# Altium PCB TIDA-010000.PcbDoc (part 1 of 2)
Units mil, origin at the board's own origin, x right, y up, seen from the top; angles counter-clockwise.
Board outline 6158.37 x 2561.06 mil, 2 copper layers (Top Layer, Bottom Layer), stack 62 mil thick; 145 components, 51 nets, 285 pads, 57 vias.
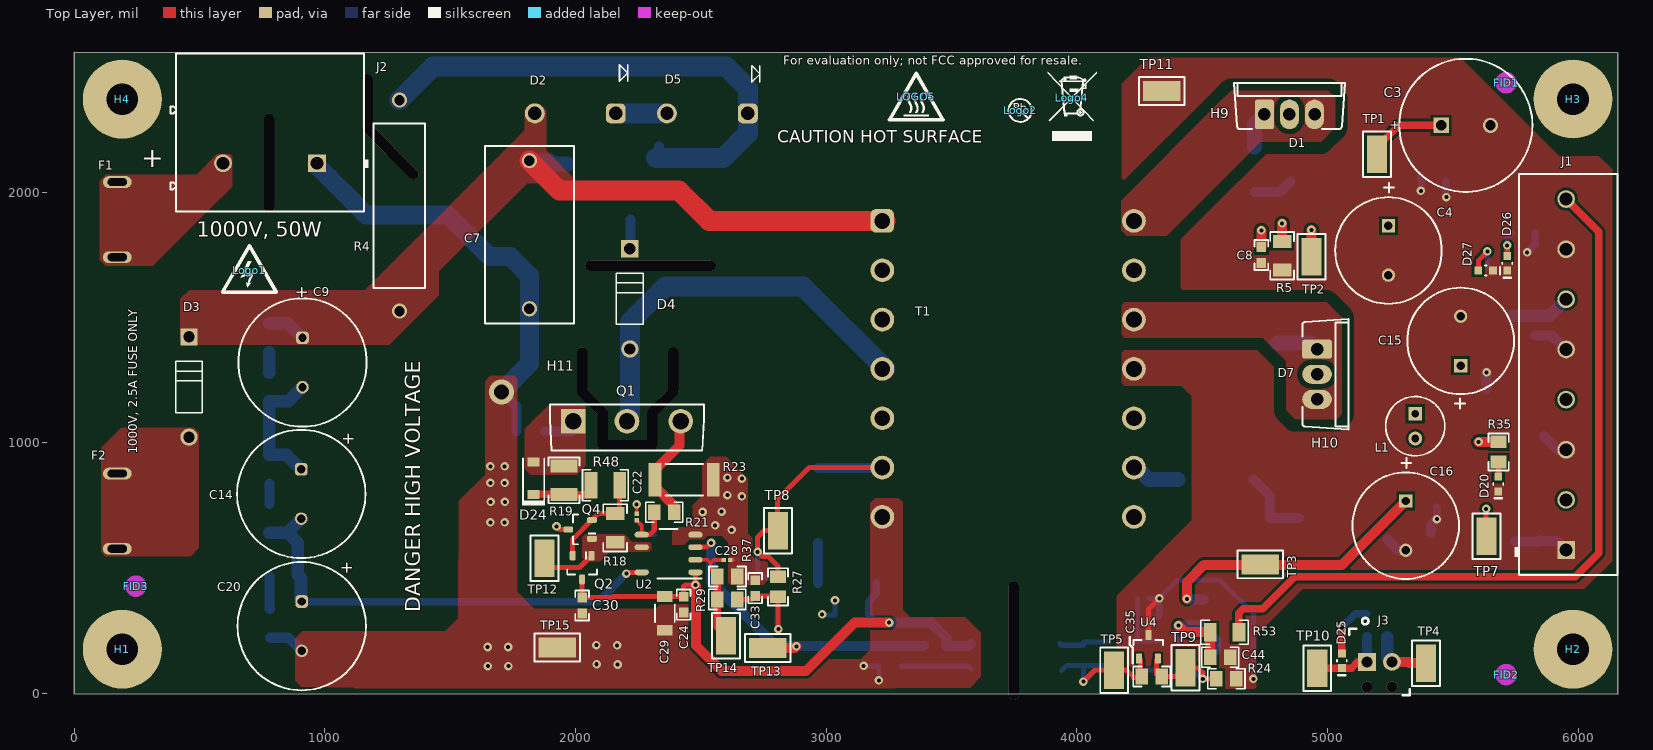
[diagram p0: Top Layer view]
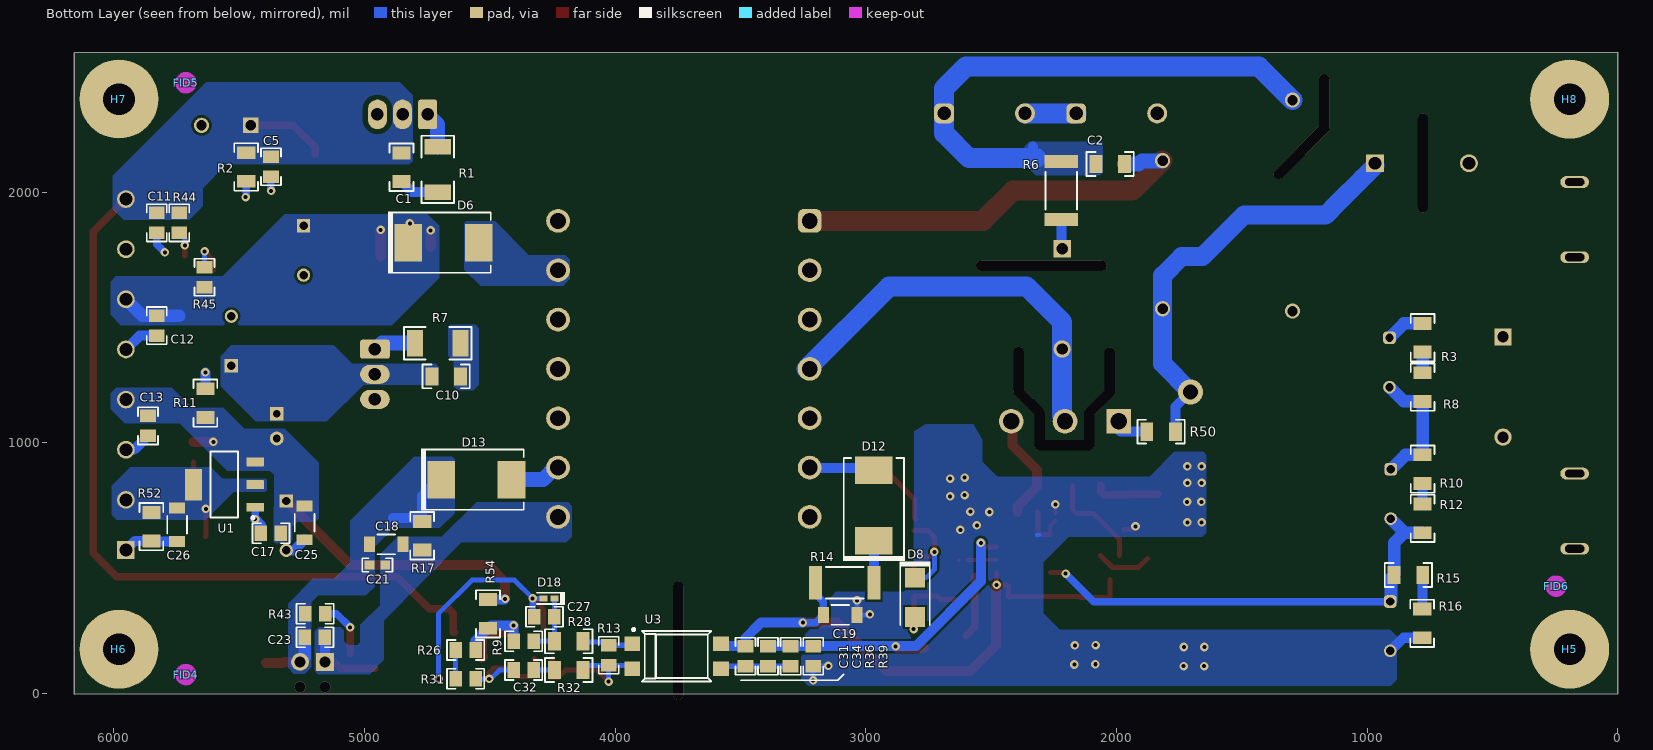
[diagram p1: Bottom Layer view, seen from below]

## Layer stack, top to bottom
Top Solder: solder mask 0.4, Solder Resist, Dk 3.5
Top Layer: signal copper 1.4
Dielectric1: core 59.2, FR-4 Hign Tg, Dk 4.8
Bottom Layer: signal copper 1.4
Bottom Solder: solder mask 0.4, Solder Resist, Dk 3.5

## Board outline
0,0 6158.37,-2 6157.71,2557.06 0,2559.06

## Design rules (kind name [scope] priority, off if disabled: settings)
AcuteAngle [All] p1: minimum=4.50000000000000E+0001 checktracksonly=FALSE
AssemblyTestPointUsage [All] p1: valid=2
BoardOutlineClearance [All] p1: gap=15 ignorepadtopadclearanceinfootprint=FALSE
Clearance "24V Diode" [InNet('24VDC') vs InNet('NetD1_1')] p1: gap=19.68 ignorepadtopadclearanceinfootprint=FALSE
Clearance 5V_Diode [InNet('NetD7_1') vs InNet('NetC10_1')] p2: gap=19.68 ignorepadtopadclearanceinfootprint=FALSE
Clearance Sec_Diode [(InNet('NetD1_1') OR InNet('NetD6_2') OR InNet('NetD7_1')) vs InNet('GND')] p3: gap=49.21 ignorepadtopadclearanceinfootprint=FALSE
Clearance HV_PGND_CLEARANCE [(InNet('VDC') OR InNet('NetC2_2')) vs InNet('PGND')] p4: gap=314.96 ignorepadtopadclearanceinfootprint=FALSE except(0: Text-Hole; 10: Text-Text)
Clearance Clearance_Poly [InPolygon] p5: gap=10 ignorepadtopadclearanceinfootprint=FALSE except(0: Arc-Hole Track-Hole SMDPad-Hole THPad-Hole Via-Hole Fill-Hole Poly-Hole Region-Hole Text-Hole; 15: SMDPad-SMDPad; 25: Arc-Arc Arc-Track Arc-SMDPad Arc-THPad Arc-Via Arc-Text Track-Track Track-SMDPad Track-THPad Track-Via Track-Text SMDPad-THPad SMDPad-Via SMDPad-Text THPad-THPad THPad-Via Via-Via Via-Text Fill-Text Poly-Text Region-Text Text-Text)
Clearance HV_NET [InNet('HV_START')] p6: gap=62.99 ignorepadtopadclearanceinfootprint=FALSE
Clearance Clearance_Keepouts [((IsTrack Or IsArc) And Not InPoly) And IsFree and IsKeepOut vs ((IsTrack Or IsArc) And Not InPoly) And IsFree and IsKeepOut] p7: gap=0 ignorepadtopadclearanceinfootprint=FALSE
Clearance Clearance_FiducialMark [IsKeepOut and InComponentClass('FiducialMark') vs IsPad and InComponentClass('FiducialMark')] p8: gap=0 ignorepadtopadclearanceinfootprint=FALSE
Clearance samenet [All] p9: gap=7.87 ignorepadtopadclearanceinfootprint=FALSE except(0: Arc-Hole Track-Hole SMDPad-Hole THPad-Hole Via-Hole Fill-Hole Poly-Hole Region-Hole Text-Hole; 20: THPad-Fill THPad-Poly THPad-Region)
Clearance [All] p10: gap=7.87 ignorepadtopadclearanceinfootprint=FALSE except(0: Arc-Hole Track-Hole SMDPad-Hole THPad-Hole Via-Hole Fill-Hole Poly-Hole Region-Hole Text-Hole; 10: Fill-Fill Fill-Poly Fill-Region Poly-Poly Poly-Region Region-Region; 20: THPad-Fill THPad-Poly THPad-Region)
ComponentClearance ComponentClearance_MountingHoles_FiducialMarks [InComponentClass('Mounting Holes') vs InComponentClass('FiducialMark')] p1: gap=10 collisioncheckmode=3 verticalgap=10 showdistances=FALSE
ComponentClearance ComponentClearance_Shunt [InComponentClass('Header') vs InComponentClass('Shunt')] p2: gap=0 collisioncheckmode=3 verticalgap=0 showdistances=FALSE
ComponentClearance ComponentClearance_Logo [InComponentClass('Logo')] p3: gap=10 collisioncheckmode=3 verticalgap=10 showdistances=FALSE
ComponentClearance ComponentClearance_ScrewToNut [(HasFootprint('NY PMS 440 0025 PH')) vs (HasFootprint('Keystone_1902C'))] p4: gap=5 collisioncheckmode=3 verticalgap=10 showdistances=FALSE
ComponentClearance ComponentClearance_MountingHoles [InComponentClass('Mounting Holes')] p5: gap=250 collisioncheckmode=3 verticalgap=100000 showdistances=FALSE
ComponentClearance ComponentClearance_SmallPassives [HasFootprint('0201*') or HasFootprint('0402*') or HasFootprint('0508') or HasFootprint('0603*') or HasFootprint('0612') or HasFootprint('0805*') or HasFootprint('0815*') or HasFootprint('0830*') or HasFootprint('1206*') or HasFootprint('1210*') or HasFootprint('1808*') or HasFootprint('1812*') or HasFootprint('1825*') or HasFootprint('2010*') or HasFootprint('2220*') or HasFootprint('2225*') or HasFootprint('2512*') or HasFootprint('2728*') or HasFootprint('3518*') vs HasFootprint('0201*') or HasFootprint('0402*') or HasFootprint('0508') or HasFootprint('0603*') or HasFootprint('0612') or HasFootprint('0805*') or HasFootprint('0815*') or HasFootprint('0830*') or HasFootprint('1206*') or HasFootprint('1210*') or HasFootprint('1808*') or HasFootprint('1812*') or HasFootprint('1825*') or HasFootprint('2010*') or HasFootprint('2220*') or HasFootprint('2225*') or HasFootprint('2512*') or HasFootprint('2728*') or HasFootprint('3518*')] p6: gap=12 collisioncheckmode=3 verticalgap=10 showdistances=FALSE
ComponentClearance ComponentClearance_THtoSMT [IsThruComponent vs IsSMTComponent] p7: gap=20 collisioncheckmode=3 verticalgap=30 showdistances=FALSE
ComponentClearance ComponentClearance_THtoTH [IsThruComponent vs IsThruComponent] p8: gap=20 collisioncheckmode=3 verticalgap=30 showdistances=FALSE
ComponentClearance [All] p9: gap=20 collisioncheckmode=3 verticalgap=10 showdistances=FALSE
DiffPairsRouting [All] p1: maxlimit=100 minlimit=10 mostfreqgap=10 toplayer_minwidth=15 toplayer_maxwidth=15 toplayer_prefwidth=15 bottomlayer_minwidth=15 bottomlayer_maxwidth=15 bottomlayer_prefwidth=15 maxuncoupledlength=1000
FabricationTestPointUsage TestPointUsage [All] p1: valid=2 allowmultiple=FALSE
FabricationTestpoint Testpoint [All] p1: side=3 testpointundercomponent=TRUE minsize=40 maxsize=100 preferedsize=60 minholesize=0 maxholesize=40 preferedholesize=32 testpointgrid=1 allowsidetop=TRUE allowsidebottom=TRUE usegrid=TRUE gridtolerance=0.01
FanoutControl Fanout_LCC [IsLCC] p1: bgadir=Out bgaviamode=Centered fanoutstyle=Auto fanoutdirection=Alternating viagrid=1 // Fanout_LCC (Default Rule)
FanoutControl Fanout_BGA [IsBGA] p2: bgadir=Out bgaviamode=Centered fanoutstyle=Auto fanoutdirection=Alternating viagrid=1 // Fanout_BGA (Default Rule)
FanoutControl Fanout_Default [All] p4: bgadir=Out bgaviamode=Centered fanoutstyle=Auto fanoutdirection=Alternating viagrid=1 // Fanout_Default (Default Rule)
FanoutControl Fanout_Small [(CompPinCount < 5)] p5: bgadir=Out bgaviamode=Centered fanoutstyle=Auto fanoutdirection=OutThenIn viagrid=1 // Fanout_Small (Default Rule)
HoleSize [All] p1: absolutevalues=TRUE maxlimit=251 minlimit=7.87 maxpercent=80.000 minpercent=20.000
MinimumAnnularRing MinimumAnnularRing_ThermalPadVias [IsVia and InAnyComponent] p1: minimumring=5.91
MinimumAnnularRing [All] p2: minimumring=8
MinimumSolderMaskSliver MinimumSolderMaskSliver_Logo [InComponentClass('Logo') vs InComponentClass('Logo')] p1: minsoldermaskwidth=0.7
MinimumSolderMaskSliver [All] p2: minsoldermaskwidth=3.94
PlaneConnect [All] p1: planeconnectstyle=Relief reliefexpansion=10 reliefentries=4 reliefconductorwidth=10 reliefairgap=10
PolygonConnect [All] p1: connectstyle=Direct reliefconductorwidth=10 reliefentries=4 polygonreliefangle="90 Angle" airgapwidth=10
RoutingVias ThermalPadVias [IsVia and InAnyComponent] p1: holewidth=7.87 width=19.68 viastyle="Through Hole" minholewidth=7.87 minwidth=19.68 maxholewidth=12.99 maxwidth=23.62
RoutingVias [All] p2: holewidth=16 width=34 viastyle="Through Hole" minholewidth=7.87 minwidth=26 maxholewidth=40 maxwidth=65
SilkToBoardRegionClearance [Not ((IsComment or IsDesignator) And (Hide <> 'False')) and not InRegion(1000,500,4000,800)] p1:
SilkToSilkClearance SilkToSilkClearance_Pb-FreeLogo [(HasFootprint('Pb-Free_Overlay_Medium') OR HasFootprint('Pb-Free_Overlay_Small')) vs (HasFootprint('Pb-Free_Overlay_Medium') OR HasFootprint('Pb-Free_Overlay_Small'))] p1: silktosilkclearance=0
SilkToSilkClearance [All] p2: silktosilkclearance=4
SilkToSolderMaskClearance SilkToComponentPadClearance [(IsPad or IsFill or IsRegion) and InAnycomponent] p1: minsilkscreentomaskgap=5 clearancetoexposedcopper=TRUE
SilkToSolderMaskClearance "Silk to Solder Mask Opening" [All] p2: minsilkscreentomaskgap=4 clearancetoexposedcopper=FALSE
SolderMaskExpansion [All] p1: expansion=1.97
Width [All] p1: maxlimit=100 minlimit=6 preferedwidth=10 checkconnectedcopper=TRUE
15 further rules are at their usual default settings.

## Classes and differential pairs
component class AssemblyNote: ZZ1 ZZ2 ZZ3 ZZ4
component class FiducialMark: FID1 FID2 FID3 FID4 FID5 FID6
component class EVM_Hardware: FID1 FID2 FID3 FID4 FID5 FID6 H1 H2 H3 H4 H5 H6 H7 H8 Logo1 Logo2 Logo3 Logo4 LOGO5 ZZ1 ZZ2 ZZ3 ZZ4
component class "Mounting Holes": H1 H2 H3 H4
component class "Pg1 Flyback Converter": C1 C2 C3 C4 C5 C7 C8 C9 C10 C11 C12 C13 C14 C15 C16 C17 C18 C19 C20 C21 C22 C23 C24 C25 C26 C27 C28 C29 C30 C31 C32 C33 C34 C35 C44 D1 D2 D3 D4 D5 D6 D7 D8 D12 D13 D18 D20 D24 D25 D26 D27 F1 F2 H9 H10 H11 J1 J2 J3 L1 Q1 Q2 Q4 R1 R2 R3 R4 R5 R6 R7 R8 R9 R10 R11 R12 R13 R14 R15 R16 R17 R18 R19 R21 R23 R24 R26 R27 R28 R29 R31 R32 R35 R36 R37 R39 R43 R44 R45 R48 R50 R52 R53 R54 T1 TP1 TP2 TP3 TP4 TP5 TP7 TP8 TP9 TP10 TP11 TP12 TP13 TP14 TP15 U1 U2 U3 U4

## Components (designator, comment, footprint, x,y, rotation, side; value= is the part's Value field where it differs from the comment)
C1 "GRM31A5C2J331JW01D" 1206 4852.44,2100 r270 bottom value=330pF
C2 "GRM31BR73A472KW01L" 1206 2025.22,2113 r0 bottom value=4700pF
C3 "UBT1H471MHD1TO" BT_1250x2500 5551.83,2267 r0 top value=470uF
C4 "UBT1V331MPD1TD" BT_1000x2000 5243.22,1768 r270 top value=330uF
C5 "C0805C104K5RACTU" 0805_HV 5373.31,2102 r270 bottom value=0.1uF
C7 "B32672L1333J000" B32672_1800x900x1750 1816.22,1831 r270 top value=0.033uF
C8 "GMK107AB7105KAHT" 0603 4736.22,1750 r270 top value=1uF
C9 "450BXW47MEFC12.5X35" BXW_1250x3500 910.91,1321 r270 top locked value=47uF
C10 "GRM31A5C2J331JW01D" 1206 4674.22,1265.52 r180 bottom value=330pF
C11 "C0805C104K5RACTU" 0805_HV 5829.16,1878 r270 bottom value=0.1uF
C12 "C0805C104K5RACTU" 0805_HV 5829.16,1468 r270 bottom value=0.1uF
C13 "C0805C104K5RACTU" 0805_HV 5863.88,1068 r270 bottom value=0.1uF
C14 "450BXW47MEFC12.5X35" BXW_1250x3500 905.91,796.53 r270 top locked value=47uF
C15 "UBT1E471MPD1TD" BT_1000x2000 5531.22,1407 r90 top value=470uF
C16 "UBT1E471MPD1TD" BT_1000x2000 5312.22,670 r270 top value=470uF
C17 "GRM219R71E105KA88D" 0805_HV 5373.31,640 r0 bottom value=1uF
C18 "C3216X7R1E106M160AE" 1206_190 4913.22,595.76 r180 bottom value=10uF
C19 "C3216X7R1V106K160AC" 1206_180 3102.22,314 r180 bottom value=10uF
C20 "450BXW47MEFC12.5X35" BXW_1250x3500 907.91,269 r270 top value=47uF
C21 "C1608X7R1E104K080AA" 0603 4948.83,513 r180 bottom value=0.1uF
C22 "GRM033R71E151KA01D" 0201 2244.22,704.9 r90 top value=150pF
C23 "C0805C104K5RACTU" 0805_HV 5197.88,225 r180 bottom value=0.1uF
C24 "GMK107AB7105KAHT" 0603 2431.22,355 r270 top value=1uF
C25 "C3216X7R1E106M160AE" 1206_190 5239.22,681 r270 bottom value=10uF
C26 "C3216X7R1E106M160AE" 1206_190 5747.88,674 r270 bottom value=10uF
C27 "C0805C104K5RACTU" 0805_HV 4282.28,307 r180 bottom value=0.1uF
C28 "GCM0335C1E220JD03D" 0201_033 2605.22,532.81 r0 top value=22pF
C29 "C3216X7R1V106K160AC" 1206_180 2356.22,320 r270 top value=10uF
C30 "GMK107AB7105KAHT" 0603 2026.65,351.4 r270 top value=1uF
C31 "C2012X7R1H474K125AB" 0805_HV 3480.09,149.18 r270 bottom value=0.47uF
C32 "C2012X7R1H474K125AB" 0805_HV 4365.09,94.18 r180 bottom value=0.47uF
C33 "C1608X7R2A102K080AA" 0603 2716.91,421 r90 top value=1000pF
C34 "08055C473JAT2A" 0805_HV 3390.09,149.18 r90 bottom value=0.047uF
C35 "08055C473JAT2A" 0805_HV 4298.69,68 r0 top value=0.047uF
C44 "C0805C104K5RACTU" 0805_HV 4572.37,145 r0 top value=0.1uF
D1 "MBR20200CTTU" TO-220AB 4848.37,2310.88 r0 top value=200V
D2 "1.5KE200A-E3/54" DO-201AA_Vertical 1837.8,2314.78 r180 top value=200V
D3 "BYX10GP-E3/54" DO-41 458.37,1223.12 r270 top value=1600V
D4 "BYX10GP-E3/54" DO-41 2216.79,1575 r270 top value=1600V
D5 "1.5KE200A-E3/54" DO-201AA_Vertical 2364.86,2314.78 r180 top value=200V
D6 "MURS320-E3/57T" SMC 4685.22,1799 r180 bottom value=200V
D7 "MBR20200CTTU" TO-220AB 4958.37,1274 r270 top value=200V
D8 "ES1D-E3/61T" SMA 2804,384 r270 bottom value=200V
D12 "MURS320-E3/57T" SMC 2968.22,751 r90 bottom value=200V
D13 "MURS320-E3/57T" SMC 4554.22,854 r180 bottom value=200V
D18 "BZT52C10T-7" SOD-523 4264.28,380 r0 bottom value=10V
D20 "LG L29K-G2J1-24-Z" "LG L29K_GREEN" 5681.14,836 r270 top value=Green
D24 "BAT41ZFILM" SOD-123 1833.22,859 r90 top value=100V
D25 "LG L29K-G2J1-24-Z" "LG L29K_GREEN" 5057.37,131 r270 top value=Green
D26 "LG L29K-G2J1-24-Z" "LG L29K_GREEN" 5717.22,1717 r270 top value=Green
D27 "LG L29K-G2J1-24-Z" "LG L29K_GREEN" 5631.22,1688 r0 top value=Green
F1 "FC-102-22" BelFuse_FC-102-22 172.11,1891 r90 top
F2 "FC-102-22" BelFuse_FC-102-22 172.11,728 r90 top
FID1 "Fiducial" Fiducial10-20 5712.73,2437 r0 top
FID2 "Fiducial" Fiducial10-20 5712.73,76 r0 top
FID3 "Fiducial" Fiducial10-20 246.54,429 r0 top
FID4 "Fiducial" Fiducial10-20 5712.73,76 r180 bottom
FID5 "Fiducial" Fiducial10-20 5712.73,2437 r180 bottom
FID6 "Fiducial" Fiducial10-20 246.54,429 r180 bottom
H1 "NY PMS 440 0025 PH" "NY PMS 440 0025 PH"#1 192.11,177 r0 top locked
H2 "NY PMS 440 0025 PH" "NY PMS 440 0025 PH"#2 5979.64,173 r0 top locked
H3 "NY PMS 440 0025 PH" "NY PMS 440 0025 PH"#3 5980.15,2372.05 r0 top locked
H4 "NY PMS 440 0025 PH" "NY PMS 440 0025 PH"#1 192.11,2371.56 r0 top locked
H5 "1902C" Keystone_1902C 192.11,177 r180 bottom
H6 "1902C" Keystone_1902C 5979.64,177 r180 bottom
H7 "1902C" Keystone_1902C 5980.15,2372.05 r180 bottom
H8 "1902C" Keystone_1902C 192.11,2371.56 r180 bottom
H9 "274-2AB" HSINK_274-2AB 4832.76,2468 r180 top
H10 "274-2AB" HSINK_274-2AB 5150.83,1276 r90 top
H11 "V2109B" Assman_V2109B 2205.22,1205 r180 top locked
J1 "9993960000" Weidmuller_9993960000 5952.16,1273 r90 top locked
J2 "1902547" Phoenix_1902547 781.37,2238.11 r180 top
J3 "1725656" CONN_1725656 5207.31,126.5 r0 top locked
L1 "7447462022" WE-TI_5075 5350.22,1067.1 r270 top value=2.2uH
Logo1 "DANGER HIGH VOLTAGE" IEC_HighVoltage_Small 699,1689.44 r0 top (schematic designator LOGO1)
Logo2 "Pb-Free Symbol" Pb-Free_Overlay_Small 3774.22,2327 r0 top
Logo3 "FCC disclaimer" FCC_disclaimer 2857.28,2877 r0 top
Logo4 "WEEE logo" WEEE_Minimum 3980.22,2377 r0 top
LOGO5 "CAUTION HOT SURFACE" IEC_HotSurface_Small 3359.37,2382 r0 top
Q1 "2SK1835-E" TO-3P 2205.37,1086.79 r0 top value=1500V
Q2 "DNBT8105-7" SOT-23 2026.22,503 r270 top value="60 V"
Q4 "DPBT8105-7" SOT-23 2018.36,655 r180 top value="60 V"
R1 "CRCW2010220RJNEF" 2010 4708.22,2091 r270 bottom value=220
R2 "CRCW120610K0JNEA" 1206 5472.31,2101 r90 bottom value=10k
R3 "CRCW1206470KJNEA" 1206 778.91,1419.69 r90 bottom value=470k
R4 "PR03000202003JAC00" PR03 1298.11,1947 r270 top value=200k
R5 "CRCW120610K0JNEA" 1206 4819.22,1747 r90 top value=10k
R6 "ERJ-1TYJ100U" 2512 2220.22,2007 r90 bottom value=10
R7 "CRCW2010220RJNEF" 2010 4708.22,1398 r180 bottom value=220
R8 "CRCW1206470KJNEA" 1206 778.91,1222.69 r90 bottom value=470k
R9 "CRCW08054K02FKEA" 0805_HV 4365.37,209 r0 bottom value=4.02k
R10 "CRCW1206470KJNEA" 1206 778.91,895.77 r90 bottom value=470k
R11 "CRCW120610K0JNEA" 1206 5634.88,1159 r270 bottom value=10k
R12 "CRCW1206470KJNEA" 1206 778.91,699.13 r90 bottom value=470k
R13 "CRCW08051K00JNEA" 0805_HV 4025.9,153 r90 bottom value=1.0k
R14 "CRCW25125R11FKEG" 2512 3084.22,442 r180 bottom value=5.11
R15 "CRCW1206470KJNEA" 1206 835.59,473.5 r0 bottom value=470k
R16 "CRCW1206470KJNEA" 1206 780.59,280 r90 bottom value=470k
R17 "CRCW12061K00JNEA" 1206 4770,630 r90 bottom value=1.0k
R18 "CRCW12060000Z0EA" 1206 2158.22,661 r270 top value=0
R19 "CRCW12101R00FKEAHP" 1210 1954.13,851 r90 top value=1.00
R21 "CRCW0805560RJNEA" 0805_HV 2354.22,723.9 r180 top value=560
R23 "ERJ-1TRQFR62U" 2512 2433.22,854 r180 top value=0.62
R24 "RT0805BRD075K1L" 0805_HV 4596.7,59.18 r180 top value=5.10k
R26 "CRCW080510R0JNEA" 0805_HV 4596.7,174.18 r180 bottom value=10
R27 "CRCW0805100RFKEA" 0805_HV 2808.22,426 r90 top value=100
R28 "CRCW1206470RJNEA" 1206 4185.09,209.18 r0 bottom value=470
R29 "CRCW080544K2FKEA" 0805_HV 2605.22,376 r0 top value=44.2k
R31 "RT0805BRD0744K2L" 0805_HV 4596.7,59.18 r0 bottom value=44.2k
R32 "CRCW120610K0JNEA" 1206 4185.09,94.18 r180 bottom value=10k
R35 "CRCW08052K00FKEA" 0805_HV 5682.88,964 r90 top value=2.00k
R36 "CRCW0805100KFKEA" 0805_HV 3300.09,149.18 r270 bottom value=100k
R37 "CRCW080517K8FKEA" 0805_HV 2606.22,467 r180 top value=17.8k
R39 "CRCW080522K1FKEA" 0805_HV 3210.09,149.18 r90 bottom value=22.1k
R43 "CRCW08052K00FKEA" 0805_HV 5196.88,319 r0 bottom value=2.00k
R44 "CRCW080511K0JNEA" 0805_HV 5739.16,1878 r90 bottom value=11k
R45 "CRCW08056K80JNEA" 0805_HV 5638.72,1661 r270 bottom value=6.8k
R48 "CRCW121010R0FKEA" 1210 2119.17,831 r180 top value=10.0
R50 "CRCW12064K87FKEA" 1206 1822.22,1045 r0 bottom value=4.87k
R52 "CRCW120610K0JNEA" 1206 5850.22,666 r90 bottom value=10k
R53 "CRCW12060000Z0EA" 1206 4589.37,245 r0 top value=0
R54 "CRCW12060000Z0EA" 1206 4507.37,318 r90 bottom value=0
T1 "750343917" Wurth_ETD34_5455 3726,1295.45 r0 top value=2.5mH
TP1 "5019" Keystone_5019 5197.22,2151 r270 top
TP2 "5019" Keystone_5019 4936.22,1743 r90 top
TP3 "5019" Keystone_5019 4732,516 r0 top
TP4 "5019" Keystone_5019 5393.37,122 r270 top
TP5 "5019" Keystone_5019 4149.22,94 r90 top
TP7 "5019" Keystone_5019 5634.72,627 r90 top
TP8 "5019" Keystone_5019 2807.22,650 r90 top
TP9 "5019" Keystone_5019 4433.37,103 r90 top
TP10 "5019" Keystone_5019 4959.22,102 r90 top
TP11 "5019" Keystone_5019 4338,2404.58 r0 top
TP12 "5019" Keystone_5019 1875.72,540 r270 top
TP13 "5019" Keystone_5019 2767.22,182 r180 top
TP14 "5019" Keystone_5019 2600.22,231 r270 top
TP15 "5019" Keystone_5019 1926.74,184 r180 top
U1 "TLV1117-33IDCY" DCY0004A_N 5559.22,834 r0 bottom
U2 "UCC28740DR" D0007A_N 2371.22,559 r180 top
U3 "LTV-817S" DIP254P762X350-4 3755.09,149.18 r180 bottom
U4 "TL431BIDBZT" DBZ0003A_N 4285.7,187 r90 top
ZZ1 "This Assembly Note is for PCB labels only" AssemblyNoteLabel -505.44,3732.15 r0 top
ZZ2 "These assemblies are ESD sensitive, ESD precautions shall be observed." AssemblyNote -716.44,3645.26 r0 top
ZZ3 "These assemblies must be clean and free from flux and all contaminants. Use of no clean flux is not acceptable." AssemblyNote -716.44,3556.7 r0 top
ZZ4 "These assemblies must comply with workmanship standards IPC-A-610 Class 2, unless otherwise specified." AssemblyNote -716.44,3468.15 r0 top

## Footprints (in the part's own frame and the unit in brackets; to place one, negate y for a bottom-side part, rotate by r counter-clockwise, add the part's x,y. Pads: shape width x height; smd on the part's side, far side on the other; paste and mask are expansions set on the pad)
0201 [mm] "Data from Kemet datasheet CC101_COM dated 7/28/11"
  rect 0.46x0.42 smd mask+0.048: 1(-0.33,0) 2(0.33,0)
  body extent -0.31,-0.16 0.31,0.16, height 0.26
0201_033 [mm] "SMD, 2-Leads, Height 0.33mm"
  rect 0.46x0.42 smd mask+0.048: 1(-0.33,0) 2(0.33,0)
  body extent -0.31,-0.16 0.31,0.16, height 0.33
0603 [mm] "0603 from SM-752 data"
  rect 1x0.95 smd: 1(-0.8,0) 2(0.8,0)
  silkscreen extent -1.52,-0.69 1.52,0.69, body extent -0.87,-0.47 0.87,0.47, height 1
0805_HV [mil] "0805 with 30mil clearance between pads"
  rect 50x63 smd: 1(-40,0) 2(40,0)
  silkscreen extent -74,-40 74,40, body extent -43,-29 43,29, height 57
1206 [mm] "1206 from SM-752 data"
  rect 1.3x1.85 smd: 1(-1.45,0) 2(1.45,0)
  silkscreen extent -2.4,-1.21 2.4,1.21, body extent -1.7,-0.9 1.7,0.9, height 1.35
1206_180 [mm] "1206_180"
  rect 1.1x1.6 smd: 1(-1.7,0) 2(1.7,0)
  silkscreen extent -0.9,-1 0.9,1, body extent -1.75,-0.95 1.75,0.95, height 1.8
1206_190 [mm] "1206_190"
  rect 1.1x1.6 smd: 1(-1.7,0) 2(1.7,0)
  silkscreen extent -0.9,-1 0.9,1, body extent -1.75,-0.95 1.75,0.95, height 1.9
1210 [mm] "1210 from SM-752 data"
  rect 1.3x2.7 smd: 1(-1.45,0) 2(1.45,0)
  silkscreen extent -2.32,-1.57 2.32,1.57, body extent -1.7,-1.35 1.7,1.35, height 1.35
2010 [mm] "Chip Capacitor, Body 5.08x2.54mm, IPC Medium Density"
  rect 1.6x2.7 smd: 1(-2.3,0) 2(2.3,0)
  silkscreen extent -3.42,-1.65 3.42,1.65, body extent -2.73,-1.45 2.73,1.45, height 1.66
2512 [mm] "Chip Resistor, Body 6.3x3.2mm, IPC Medium Density"
  rect 1.3x3.4 smd: 1(-2.95,0) 2(2.95,0)
  silkscreen extent -1.9,-1.6 1.9,1.6, body extent -3.22,-1.67 3.22,1.67, height 0.71
AssemblyNote [mil] "Assembly Note"
AssemblyNoteLabel [mil] "Assembly Note for PCB Labels"
Assman_V2109B [mil] "Heat Sink TO-220 Aluminum Board Level"
  body extent -500,-25 500,475, height 1180
B32672_1800x900x1750 [mm] "TH, 2-Leads, Body 18x9mm, Lead Spacing 15mm"
  round 1.55 hole 1.05: 1(-7.5,0) 2(7.5,0)
  silkscreen extent -9,-4.5 9,4.5, body extent -9,-4.5 9,4.5, height 17.5
BelFuse_FC-102-22 [mm] "FUSE CLIP CARTRIDGE 15A PCB"
  oval 1.2x2.925 hole 0.8 slot 1.95 at 90 deg: 1(-3.81,0) 2(3.81,0)
  body extent -4.06,-3.99 4.06,3.99, height 10.79
BT_1000x2000 [mm] "TH, 2-Leads, Dia 10mm, Pin Spacing 5mm"
  rect 1.35x1.35 hole 0.85: 1(-2.5,0)
  round 1.35 hole 0.85: 2(2.5,0)
  silkscreen extent -6.86,-5.4 5.4,5.4, body extent -5.36,-5.39 5.39,5.39, height 22.01
BT_1250x2500 [mm] "TH, 2-Leads, Dia 12.5mm, Lead Sapcing 5mm"
  rect 1.55x1.55 hole 1.05: 1(-2.5,0)
  round 1.55 hole 1.05: 2(2.5,0)
  silkscreen extent -6.75,-6.75 6.75,6.75, body extent -6.7,-6.74 6.73,6.74, height 27.01
BXW_1250x3500 [mm] "TH, 2-Leads, Dia 12.5mm, Pin Spacing 5mm"
  rrect50% 1.275x1.275 hole 0.85: 1(-2.5,0)
  round 1.275 hole 0.85: 2(2.5,0)
  silkscreen extent -6.5,-6.5 6.5,6.5, body extent -6.5,-6.5 6.51,6.5, height 37.01
CONN_1725656 [mm] "Phoenix Contact"
  rect 1.8x1.8 hole 1.1: 1(-1.27,0)
  round 1.8 hole 1.1: 2(1.27,0)
  round 1.1 hole 1.1 unplated mask+0.127: MH1(-1.275,-2.54) MH2(1.27,-2.54)
  silkscreen extent -3.08,-3.37 3.08,3.37, body extent -2.77,-3.1 2.77,3.1, height 8.52
D0007A_N [mm] "SOIC, 7-Leads, Body 4.9x3.9mm, Pitch 1.27mm, IPC Medium Density"
  oval 1.45x0.6 smd: 1(-2.725,1.905) 2(-2.725,0.635) 3(-2.725,-0.635) 4(-2.725,-1.905) 5(2.725,-1.905) 6(2.725,-0.635) 8(2.725,1.905)
  silkscreen extent -3.32,-2.5 1.1,2.52, body extent -3.01,-2.45 3.01,2.45, height 1.75
DBZ0003A_N [mm] "SOT23, 3-Leads, Body 2.9x1.3mm, Pitch 0.95mm, Lead Span 2.4mm, IPC Medium Density"
  rrect17% 1x0.6 smd: 1(-1.2,0.95) 2(-1.2,-0.95) 3(1.2,0)
  silkscreen extent 0.2,-1.5 0.7,1.5, body extent -1.26,-1.46 1.26,1.46, height 0.98
DCY0004A_N [mm] "SOT223/SC73, 4-Leads, Body 6.5x3.5mm, Pitch 2.3mm, Lead Span 7mm, IPC Medium Density"
  rrect11% 1.75x0.9 smd: 1(-3.125,2.3) 2(-3.125,0) 3(-3.125,-2.3)
  rrect6% 1.75x3.2 smd: 4(3.125,0)
  silkscreen extent -3.02,-3.35 1.4,3.47, body extent -3.48,-3.25 3.48,3.25, height 1.68
DIP254P762X350-4 [mm] "LITE-ON"
  rect 1.6x1.5 smd: 1(-4.5,1.27) 2(-4.5,-1.27) 3(4.5,-1.27) 4(4.5,1.27)
  silkscreen extent -4.47,-2.55 3.5,2.82, body extent -5.23,-2.55 5.23,2.55, height 4.62
DO-41 [mm] "diode"
  rect 1.75x1.75 hole 1.15: 1(-5.08,0)
  round 1.75 hole 1.15: 2(5.08,0)
  silkscreen extent -2.62,-1.37 2.59,1.35, body extent -5.51,-1.36 5.51,1.36, height 2.72
DO-201AA_Vertical [mm] "TH, 2-Leads, Dia 5.05mm"
  rrect50% 2.025x2.025 hole 1.35: 1(-8.2,0)
  round 2.025 hole 1.35: 2(0,0)
  body extent -8.73,-2.65 2.65,2.66, height 14.17
FCC_disclaimer [mil]
Fiducial10-20 [mm]
  round 1 smd mask+0.5: 1(0,0)
  Top Layer keep-out circle w1.178: c0,0 r0.5
HSINK_274-2AB [mil] "HEATSINK LOW HEIGHT BLK TO-220"
  body extent -260,-25 260,475, height 750
IEC_HighVoltage_Small [mil]
  silkscreen extent -107,-88 107,97
IEC_HotSurface_Small [mil]
  silkscreen extent -107,-93 107,92
Keystone_1902C [mil] "Hex Standoff, 4-40 threaded, nylon"
  round 1 on Mech4: 0(0,0)
  body extent -145,-126 146,126, height 501
Keystone_5019 [mm] "Test Point, Miniature, SMT"
  rect 3.8x2.03 smd: 1(0,0)
  silkscreen extent -2.31,-1.42 2.31,1.42, body extent -1.9,-1.02 1.9,1.02, height 2.29
"LG L29K_GREEN" [mm] "OSRAM"
  rect 0.8x0.8 smd paste-0.4: 1(-0.75,0) 2(0.75,0)
  silkscreen extent -0.1,-0.5 1.45,0.5, body extent -0.9,-0.45 0.9,0.45, height 0.67
"NY PMS 440 0025 PH"#1 [mm] "4-40 nylon screw and mounting hole"
  round 8 hole 3.2 unplated: 1(0,0)
  body extent -3.3,-3.3 3.3,3.3, height 2.69
"NY PMS 440 0025 PH"#2 [mm] "4-40 nylon screw and mounting hole"
  round 8 hole 3.2: 1(0,0.102)
  body extent -3.3,-3.3 3.3,3.3, height 2.69
"NY PMS 440 0025 PH"#3 [mm] "4-40 nylon screw and mounting hole"
  round 8 hole 3.2 unplated: 1(-0.013,0)
  body extent -3.3,-3.3 3.3,3.3, height 2.69
Pb-Free_Overlay_Small [mil]
  silkscreen extent -46,-46 46,46
Phoenix_1902547 [mm] "TH, 2-Leads, Body 19.04x16mm, Pitch 9.52mm"
  rect 1.8x1.8 hole 1.3: 1(-4.76,3.1)
  round 1.8 hole 1.3: 2(4.76,3.1)
  silkscreen extent -10,-8 10.09,8, body extent -9.52,-8 10.09,8, height 22
PR03 [mm] "TH, 2-Leads, Axial, Dia 5.2mm, Pin Spacing 21.38mm"
  round 1.55 hole 1.05: 1(-10.69,0) 2(10.69,0)
  silkscreen extent -8.34,-2.63 8.36,2.57, body extent -11.08,-2.6 11.08,2.6, height 5.22
SMA [mm] "Molded Diode, 2-Leads, Body 4.3x2.6mm, IPC Medium Density, based on OnSemi component dimensions and land pattern"
  rect 2x2 smd: 1(-2,0) 2(2,0)
  silkscreen extent -3.66,-1.57 2.79,1.57, body extent -2.6,-1.3 2.6,1.3, height 2.42
SMC [mil] "Molded Diode, 2-Leads, Body 6.9x5.8mm, IPC Medium Density, based on OnSemi component dimensions and land patterns"
  rect 110x150 smd: 1(-140.49,0) 2(140.49,0)
  silkscreen extent -221,-123 189,124, body extent -156,-116 156,116, height 91
SOD-123 [mm] "On Semi recommended land pattern"
  rect 0.915x1.22 smd: 1(-1.637,0) 2(1.637,0)
  silkscreen extent -2.74,-1.17 2.03,1.17, body extent -1.93,-0.9 1.93,0.9, height 1.35
SOD-523 [mm] "NXP Semiconductor recommended land pattern, nominal STEP model"
  rect 0.8x0.6 smd paste-0.05: 1(-0.55,0) 2(0.55,0)
  silkscreen extent -1.65,-0.66 1.2,0.66, body extent -0.8,-0.4 0.8,0.4, height 0.72
SOT-23 [mm] "SOT23, 3-Leads, Body 2.9x1.3mm, Pitch 0.95mm, Lead Span 2.5mm, IPC Medium Density"
  rrect50% 1x0.6 smd: 1(-1.2,0.95) 2(-1.2,-0.95) 3(1.2,0)
  silkscreen extent -1.63,-1.5 0.7,1.5, body extent -1.16,-1.45 1.21,1.45, height 1
TO-3P [mm] "IXYS"
  rrect4% 2.5x2.5 hole 1.65: 1(-5.45,0)
  round 2.5 hole 1.65: 2(0,0) 3(5.45,0)
  silkscreen extent -7.8,-2.99 7.8,1.71, body extent -7.8,-3.05 7.8,1.66, height 23.4
TO-220AB [mil] "Copied from Altium's version of TO3B"
  rrect25% 76x118.11 hole 50: 1(-100,0)
  oval 76x118.11 hole 50: 2(0,0) 3(100,0)
  silkscreen extent -221,-59 221,126, body extent -221,-59 221,126, height 765
WE-TI_5075 [mm] "Wurth WE-TI 5075"
  rect 1.4x1.4 hole 0.787: 1(-1.25,0)
  round 1.4 hole 0.787: 2(1.25,0)
  silkscreen extent -3,-3 3,3, body extent -3,-3 3,3, height 8.5
WEEE_Minimum [mil] "WEEElie bin"
  silkscreen extent -95,-172 99,104
Weidmuller_9993960000 [mm] "Terminal Block, 5.08mm, 8x1, TH"
  rect 1.8x1.8 hole 1.3: 1(-17.78,0)
  round 1.8 hole 1.3: 2(-12.7,0) 3(-7.62,0) 4(-2.54,0) 5(2.54,0) 6(7.62,0) 7(12.7,0) 8(17.78,0)
  silkscreen extent -20.32,-5.2 20.32,5.25, body extent -20.32,-5.2 20.92,4.8, height 13.8
Wurth_ETD34_5455 [mm] "TH, 14-Leads, Body 43.18x39.6mm"
  rrect50% 2.4x2.4 hole 1.6: 1(-12.75,15)
  round 2.4 hole 1.6: 2(-12.75,10) 3(-12.75,5) 4(-12.75,0) 5(-12.75,-5) 6(-12.75,-10) 7(-12.75,-15) 8(12.75,-15) 9(12.75,-10) 10(12.75,-5) 11(12.75,0) 12(12.75,5) 13(12.75,10) 14(12.75,15)
  body extent -21.59,-19.8 21.59,19.8, height 30.48

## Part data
C1 C10: library part CMP-0008887-2, "CAP, CERM, 330 pF, 630 V, +/- 5%, C0G/NP0, 1206", Cap_Case=1206, Manufacturer=MuRata, Supplier Part Number 1=490-5276-1-ND, TempCo=C0G/NP0, Tolerance_%=5%, Value1=Unknown, Value2=630V, ValueDisplayed=330pF
C2: library part CMP-0008920-2, "CAP, CERM, 4700 pF, 1000 V, +/- 10%, X7R, 1206", Cap_Case=1206, Manufacturer=MuRata, Supplier Part Number 1=490-3498-1-ND, TempCo=X7R, Tolerance_%=10%, Value1=Unknown, Value2=1000V, ValueDisplayed=4700pF
C3: library part CMP-0009919-2, "CAP, AL, 470 uF, 50 V, +/- 20%, 0.055 ohm, AEC-Q200 Grade 1, TH", Cap_Case=12.5x25mm, Manufacturer=Nichicon, Supplier Part Number 1=493-4510-1-ND, Tolerance_%=20%, Value1="0.055 ohm", Value2=50V, ValueDisplayed=470uF
C4: library part CMP-0010530-2, "CAP, AL, 330 uF, 35 V, +/- 20%, AEC-Q200 Grade 1, TH", Cap_Case=10x20mm, Manufacturer=Nichicon, Supplier Part Number 1=493-13112-1-ND, Tolerance_%=20%, Value1=Unknown, Value2=35V, ValueDisplayed=330uF
C5 C11 C12 C13 C23 C27 C44: library part CMP-0007726-2, "CAP, CERM, 0.1 uF, 50 V, +/- 10%, X7R, 0805", Cap_Case=0805, Manufacturer=Kemet, Supplier Part Number 1=399-1170-1-ND, TempCo=X7R, Tolerance_%=10%, Value1="0.064 ohm", Value2=50V, ValueDisplayed=0.1uF
C7: library part CMP-0080561-1, "CAP, Film, 0.033 µF, 1600 V,+/- 5%, TH", Cap_Case=18x9x17.5mm, Manufacturer=TDK, Supplier Part Number 1=495-3218-ND, Tolerance_%=5%, Value2=1600V, ValueDisplayed=0.033µF
C8 C24 C30: library part CMP-0007149-4, "CAP, CERM, 1 uF, 35 V, +/- 10%, X7R, AEC-Q200 Grade 0, 0603", Cap_Case=0603, Manufacturer="Taiyo Yuden", Supplier Part Number 1=587-3352-1-ND, TempCo=X7R, Tolerance_%=10%, Value1=Unknown, Value2=35V, ValueDisplayed=1uF
C9 C14 C20: library part CMP-0078361-1, "CAP, AL, 47 µF, 450 V, +/- 20%, TH", Cap_Case=12.5x35mm, Manufacturer=Rubycon, Supplier Part Number 1=1189-1361-ND, Tolerance_%=20%, Value2=450V, ValueDisplayed=47µF
C15 C16: library part CMP-0010529-1, "CAP, AL, 470 uF, 25 V, +/- 20%, 0.057 ohm, TH", Cap_Case=10x20mm, Manufacturer=Nichicon, Supplier Part Number 1=493-4499-1-ND, Tolerance_%=20%, Value1="0.057 ohm", Value2=25V, ValueDisplayed=470uF
C17: library part CMP-0008217-2, "CAP, CERM, 1 uF, 25 V, +/- 10%, X7R, 0805", Cap_Case=0805, Manufacturer=MuRata, Supplier Part Number 1=GRM219R71E105KA88D-ND, TempCo=X7R, Tolerance_%=10%, Value1=Unknown, Value2=25V, ValueDisplayed=1uF
C18 C25 C26: library part CMP-0008692-2, "CAP, CERM, 10 uF, 25 V, +/- 20%, X7R, 1206_190", Cap_Case=1206, Manufacturer=TDK, Supplier Part Number 1=445-6812-1-ND, TempCo=X7R, Tolerance_%=20%, Value1=Unknown, Value2=25V, ValueDisplayed=10uF
C19 C29: library part CMP-0008705-2, "CAP, CERM, 10 uF, 35 V, +/- 10%, X7R, 1206", Cap_Case=1206_180, Manufacturer=TDK, Supplier Part Number 1=445-14799-1-ND, TempCo=X7R, Tolerance_%=10%, Value1="0.002229 ohm", Value2=35V, ValueDisplayed=10uF
C21: library part CMP-0007039-5, "CAP, CERM, 0.1 uF, 25 V, +/- 10%, X7R, 0603", Cap_Case=0603, Manufacturer=TDK, Supplier Part Number 1=445-1316-1-ND, TempCo=X7R, Tolerance_%=10%, Value1=Unknown, Value2=25V, ValueDisplayed=0.1uF
C22: library part CMP-0009767-1, "CAP, CERM, 150 pF, 25 V, +/- 10%, X7R, 0201", Cap_Case=0201, Manufacturer=MuRata, Supplier Part Number 1=490-3174-1-ND, TempCo=X7R, Tolerance_%=10%, Value1=Unknown, Value2=25V, ValueDisplayed=150pF
C28: library part CMP-0009659-3, "CAP, CERM, 22 pF, 25 V, +/- 5%, C0G/NP0, AEC-Q200 Grade 1, 0201", Cap_Case=0201, Manufacturer=MuRata, Supplier Part Number 1=81-GCM0335C1E220JD3D, TempCo=C0G/NP0, Tolerance_%=5%, Value1=Unknown, Value2=25V, ValueDisplayed=22pF
C31 C32: library part CMP-0007880-2, "CAP, CERM, 0.47 uF, 50 V, +/- 10%, X7R, 0805", Cap_Case=0805, Manufacturer=TDK, Supplier Part Number 1=445-7543-1-ND, TempCo=X7R, Tolerance_%=10%, Value1="0.022012 ohm", Value2=50V, ValueDisplayed=NA
C33: library part CMP-0007053-4, "CAP, CERM, 1000 pF, 100 V, +/- 10%, X7R, 0603", Cap_Case=0603, Manufacturer=TDK, Supplier Part Number 1=445-1298-1-ND, TempCo=X7R, Tolerance_%=10%, Value1=Unknown, Value2=100V, ValueDisplayed=1000pF
C34 C35: library part CMP-0007658-2, "CAP, CERM, 0.047 uF, 50 V, +/- 5%, X7R, 0805", Cap_Case=0805, Manufacturer=AVX, Supplier Part Number 1=478-3771-1-ND, TempCo=X7R, Tolerance_%=5%, Value1="0.035 ohm", Value2=50V, ValueDisplayed=0.047uF
D1 D7: library part CMP-0077060-2, "Diode, Schottky, 200 V, 10 A, TH", Manufacturer="Fairchild Semiconductor", Supplier Part Number 1=MBR20200CTTU-ND, Value1=10A, Value2=0.9V
D2 D5: library part CMP-0082199-2, "Diode, TVS, Uni, 200 V, 274 Vc, AEC-Q101, DO-201AA", Manufacturer=Vishay-Semiconductor, Supplier Part Number 1=1.5KE200A-E3/54GICT-ND
D3 D4: library part CMP-0082148-1, "Diode, Standard Recovery Rectifier, 1600 V, 0.36 A, TH", Manufacturer=Vishay-Semiconductor, Supplier Part Number 1=BYX10GP-E3/54-ND, Value1=0.36A, Value2=1.6V
D6 D12 D13: library part CMP-0082145-1, "Diode, Ultrafast, 200 V, 3 A, AEC-Q101, SMC", Manufacturer=Vishay-Semiconductor, Supplier Part Number 1=MURS320-E3/57TGICT-ND, Value1=3A, Value2=0.875V
D8: library part CMP-0082147-1, "Diode, Ultrafast, 200 V, 1 A, AEC-Q101, SMA", Manufacturer=Vishay-Semiconductor, Supplier Part Number 1=ES1D-E3/61TGICT-ND, Value1=1A, Value2=0.92V
D18: library part CMP-0005875-3, "Diode, Zener, 10 V, 300 mW, SOD-523", Manufacturer="Diodes Inc.", Power_W=300mW, Supplier Part Number 1=BZT52C10T-7DICT-ND, Value1=0.3W
D20 D25 D26 D27: library part CMP-0002874-1, "LED, Green, SMD", Color=green, Manufacturer=OSRAM, Supplier Part Number 1=475-2709-1-ND, Value1=W, Value2=1.7V
D24: library part CMP-0028445-1, "Diode, Schottky, 100 V, 0.2 A, SOD-123", Manufacturer=STMicroelectronics, Supplier Part Number 1=497-5558-1-ND, Value1=0.2A, Value2=1V
F1 F2: library part CMP-0082195-1, "FUSE CLIP CARTRIDGE 15A PCB", Manufacturer="Bel Fuse", Supplier Part Number 1=507-1702-ND
FID1 FID2 FID3 FID4 FID5 FID6: library part CMP-0077181-1, "Fiducial mark.  There is nothing to buy or mount.", Manufacturer=N/A
H1 H2 H3 H4: library part CMP-0003617-1, "Machine Screw, Round, #4-40 x 1/4, Nylon, Philips panhead", Manufacturer="B&F Fastener Supply", Supplier Part Number 1=H542-ND
H5 H6 H7 H8: library part CMP-0003610-1, "Standoff, Hex, 0.5\"L #4-40 Nylon", Manufacturer=Keystone, Supplier Part Number 1=36-1902C-ND
H9 H10: library part CMP-0084022-1, "HEATSINK LOW HEIGHT BLK TO-220", Manufacturer=Wakefield-Vette, Supplier Part Number 1=345-1087-ND
H11: library part CMP-0082194-1, "Heat Sink TO-220 Aluminum Board Level", Manufacturer="Assman WSW", Supplier Part Number 1=A10748-ND
J1: library part CMP-0075186-1, "Terminal Block, 5.08mm, 8x1, Black, TH", Color=Black, Current_A=18A, Manufacturer=Weidmuller, Supplier Part Number 1=281-1439-ND, Voltage_V=300V
J2: library part CMP-0055527-1, "Terminal Block, 9.52mm, 2x1, R/A, TH", Color=Green, Current_A=32A, Manufacturer="Phoenix Contact", Supplier Part Number 1=277-5951-ND, Voltage_V=1kV
J3: library part CMP-0055479-1, "Terminal Block, 100mil, 2x1, 6A, 63V, TH", Manufacturer="Phoenix Contact", Supplier Part Number 1=71C4107
L1: library part CMP-0064180-1, "Inductor, Unshielded Drum Core, Ferrite, 2.2 uH, 4.3 A, 0.01 ohm, TH", Manufacturer="Wurth Elektronik", Supplier Part Number 1=732-2566-ND, Value1="0.01 ohm", Value2=4.3A, ValueDisplayed=2.2uH
Logo1: library part IEC_HighVoltage, "IEC 61010-1 High Voltage Warning"
Logo2: library part CMP-0074839-1
Logo3: library part CMP-0074847-1, "FCC_disclaimer"
Logo4: library part CMP-0074769-1
LOGO5: library part IEC_HotSurface, "IEC 61010-1 Hot Surface Warning"
Q1: library part CMP-0082176-1, "MOSFET, N-CH, 1500 V, 4 A, TO-3P", Alternate Manufacturer=None, Manufacturer=Renesas, Supplier Part Number 1=2SK1835-E-ND, Value1="? ohm", Value2="? nC"
Q2: library part CMP-0064871-1, "Transistor, NPN, 60 V, 1 A, AEC-Q101, SOT-23", Manufacturer="Diodes Inc.", Supplier Part Number 1=DNBT8105DICT-ND, Value1="1 A", Value2=300
Q4: library part CMP-0064870-1, "Transistor, PNP, 60 V, 1 A, AEC-Q101, SOT-23", Manufacturer="Diodes Inc.", Supplier Part Number 1=DPBT8105DICT-ND, Value1="1 A", Value2=300
R1 R7: library part CMP-0016095-3, "RES, 220, 5%, 0.75 W, AEC-Q200 Grade 0, 2010", Manufacturer=Vishay-Dale, Power_W=750mW, Supplier Part Number 1=541-220WCT-ND, TempCo="200 ppm/C", Tolerance_%=5%, Value2=0.75W, Value_Code=220R, ValueDisplayed=220
R2 R5 R11 R52: library part CMP-0018576-3, "RES, 10 k, 5%, 0.25 W, AEC-Q200 Grade 0, 1206", Manufacturer=Vishay-Dale, Power_W=250mW, Supplier Part Number 1=541-10KECT-ND, TempCo="200 ppm/C", Tolerance_%=5%, Value2=0.25W, Value_Code=10k0, ValueDisplayed=10k
R3 R8 R10 R12 R15 R16: library part CMP-0018684-3, "RES, 470 k, 5%, 0.25 W, AEC-Q200 Grade 0, 1206", Manufacturer=Vishay-Dale, Power_W=250mW, Supplier Part Number 1=541-470KECT-ND, TempCo="200 ppm/C", Tolerance_%=5%, Value2=0.25W, Value_Code=470k
R4: library part CMP-0014434-2, "RES, 200 k, 5%, 3 W, D5.20xL16.70mm", Manufacturer=Vishay-Bccomponents, Power_W=3W, Supplier Part Number 1=PPC200KW-3JCT-ND, TempCo="250 ppm/C", Tolerance_%=5%, Value_Code=200k
R6: library part CMP-0016023-2, "RES, 10, 5%, 1 W, 2512", Manufacturer=Panasonic, Power_W=1W, Supplier Part Number 1=PT10XCT-ND, TempCo="200 ppm/C", Tolerance_%=5%, Value_Code=10R0, ValueDisplayed=10
R9: library part CMP-0021285-3, "RES, 4.02 k, 1%, 0.125 W, AEC-Q200 Grade 0, 0805", Manufacturer=Vishay-Dale, Power_W=125mW, Supplier Part Number 1=541-4.02KCCT-ND, TempCo="100 ppm/C", Tolerance_%=1%, Value2=0.125W, Value_Code=4k02, ValueDisplayed=4.02k
R13: library part CMP-0020473-3, "RES, 1.0 k, 5%, 0.125 W, AEC-Q200 Grade 0, 0805", Manufacturer=Vishay-Dale, Power_W=125mW, Supplier Part Number 1=541-1.0KACT-ND, TempCo="200 ppm/C", Tolerance_%=5%, Value2=0.125W, Value_Code=1k00, ValueDisplayed=1.0k
R14: library part CMP-0015688-3, "RES, 5.11, 1%, 1 W, AEC-Q200 Grade 0, 2512", Manufacturer=Vishay-Dale, Power_W=1W, Supplier Part Number 1=541-5.11AFCT-ND, TempCo="100 ppm/C", Tolerance_%=1%, Value_Code=5R11, ValueDisplayed=5.11
R17: library part CMP-0018603-3, "RES, 1.0 k, 5%, 0.25 W, AEC-Q200 Grade 0, 1206", Manufacturer=Vishay-Dale, Power_W=250mW, Supplier Part Number 1=541-1.0KECT-ND, TempCo="200 ppm/C", Tolerance_%=5%, Value2=0.25W, Value_Code=1k00, ValueDisplayed=1.0k
R18 R53 R54: library part CMP-0018573-3, "RES, 0, 5%, 0.25 W, AEC-Q200 Grade 0, 1206", Manufacturer=Vishay-Dale, Power_W=250mW, Supplier Part Number 1=541-0.0ECT-ND, TempCo="200 ppm/C", Tolerance_%=5%, Value2=0.25W, Value_Code=0000, ValueDisplayed=0
R19: library part CMP-0015021-3, "RES, 1.00, 1%, 0.75 W, AEC-Q200 Grade 0, 1210", Manufacturer=Vishay-Dale, Power_W=750mW, Supplier Part Number 1=541-1.00DCT-ND, TempCo="100 ppm/C", Tolerance_%=1%, Value2=0.75W, Value_Code=1R00, ValueDisplayed=1.00
R21: library part CMP-0020569-3, "RES, 560, 5%, 0.125 W, AEC-Q200 Grade 0, 0805", Manufacturer=Vishay-Dale, Power_W=125mW, Supplier Part Number 1=541-560ACT-ND, TempCo="200 ppm/C", Tolerance_%=5%, Value2=0.125W, Value_Code=560R, ValueDisplayed=560
R23: library part CMP-0015803-2, "RES, 0.62, 1%, 1 W, 2512", Manufacturer=Panasonic, Power_W=1W, Supplier Part Number 1=PT.62YCT-ND, TempCo="200 ppm/C", Tolerance_%=1%, Value_Code=R620, ValueDisplayed=0.62
R24: library part CMP-0082196-1, "RES, 5.10 k, 0.1%, 0.125 W, 0805", Manufacturer=Yageo, Power_W=125mW, Supplier Part Number 1=YAG1938CT-ND, TempCo="25 ppm/C", Tolerance_%=0.1%, Value2=0.125W, Value_Code=5k10, ValueDisplayed=5.1k
R26: library part CMP-0020448-3, "RES, 10, 5%, 0.125 W, AEC-Q200 Grade 0, 0805", Manufacturer=Vishay-Dale, Power_W=125mW, Supplier Part Number 1=541-10ACT-ND, TempCo="200 ppm/C", Tolerance_%=5%, Value2=0.125W, Value_Code=10R0, ValueDisplayed=10
R27: library part CMP-0020835-3, "RES, 100, 1%, 0.125 W, AEC-Q200 Grade 0, 0805", Manufacturer=Vishay-Dale, Power_W=125mW, Supplier Part Number 1=541-100CCT-ND, TempCo="100 ppm/C", Tolerance_%=1%, Value2=0.125W, Value_Code=100R, ValueDisplayed=100
R28: library part CMP-0018685-3, "RES, 470, 5%, 0.25 W, AEC-Q200 Grade 0, 1206", Manufacturer=Vishay-Dale, Power_W=250mW, Supplier Part Number 1=541-470ECT-ND, TempCo="200 ppm/C", Tolerance_%=5%, Value2=0.25W, Value_Code=470R, ValueDisplayed=470
R29: library part CMP-0021262-3, "RES, 44.2 k, 1%, 0.125 W, AEC-Q200 Grade 0, 0805", Manufacturer=Vishay-Dale, Power_W=125mW, Supplier Part Number 1=541-44.2KCCT-ND, TempCo="100 ppm/C", Tolerance_%=1%, Value2=0.125W, Value_Code=44k2, ValueDisplayed=44.2k
R31: library part CMP-0020087-2, "RES, 44.2 k, 0.1%, 0.125 W, 0805", Manufacturer="Yageo America", Power_W=125mW, TempCo="25 ppm/C", Tolerance_%=0.1%, Value2=0.125W, Value_Code=44k2, ValueDisplayed=44.2k
R32: library part CMP-0018576-3, "RES, 10 k, 5%, 0.25 W, AEC-Q200 Grade 0, 1206", Manufacturer=Vishay-Dale, Power_W=250mW, Supplier Part Number 1=541-10KECT-ND, TempCo="200 ppm/C", Tolerance_%=5%, Value2=0.25W, Value_Code=10k0, ValueDisplayed=NA
R35 R43: library part CMP-0021106-3, "RES, 2.00 k, 1%, 0.125 W, AEC-Q200 Grade 0, 0805", Manufacturer=Vishay-Dale, Power_W=125mW, Supplier Part Number 1=541-2.00KCCT-ND, TempCo="100 ppm/C", Tolerance_%=1%, Value2=0.125W, Value_Code=2k00, ValueDisplayed=2.00k
R36: library part CMP-0020834-3, "RES, 100 k, 1%, 0.125 W, AEC-Q200 Grade 0, 0805", Manufacturer=Vishay-Dale, Power_W=125mW, Supplier Part Number 1=541-100KCCT-ND, TempCo="100 ppm/C", Tolerance_%=1%, Value2=0.125W, Value_Code=100k
R37: library part CMP-0020932-3, "RES, 17.8 k, 1%, 0.125 W, AEC-Q200 Grade 0, 0805", Manufacturer=Vishay-Dale, Power_W=125mW, Supplier Part Number 1=541-17.8KCCT-ND, TempCo="100 ppm/C", Tolerance_%=1%, Value2=0.125W, Value_Code=17k8, ValueDisplayed=17.8k
R39: library part CMP-0021058-3, "RES, 22.1 k, 1%, 0.125 W, AEC-Q200 Grade 0, 0805", Manufacturer=Vishay-Dale, Power_W=125mW, Supplier Part Number 1=541-22.1KCCT-ND, TempCo="100 ppm/C", Tolerance_%=1%, Value2=0.125W, Value_Code=22k1, ValueDisplayed=22.1k
R44: library part CMP-0020451-3, "RES, 11 k, 5%, 0.125 W, AEC-Q200 Grade 0, 0805", Manufacturer=Vishay-Dale, Power_W=125mW, Supplier Part Number 1=541-11KACT-ND, TempCo="200 ppm/C", Tolerance_%=5%, Value2=0.125W, Value_Code=11k0, ValueDisplayed=11k
R45: library part CMP-0020587-3, "RES, 6.8 k, 5%, 0.125 W, AEC-Q200 Grade 0, 0805", Manufacturer=Vishay-Dale, Power_W=125mW, Supplier Part Number 1=541-6.8KACT-ND, TempCo="200 ppm/C", Tolerance_%=5%, Value2=0.125W, Value_Code=6k80, ValueDisplayed=6.8k
R48: library part CMP-0015018-3, "RES, 10.0, 1%, 0.5 W, AEC-Q200 Grade 0, 1210", Manufacturer=Vishay-Dale, Power_W=500mW, Supplier Part Number 1=541-10.0AACT-ND, TempCo="100 ppm/C", Tolerance_%=1%, Value2=0.5W, Value_Code=10R0, ValueDisplayed=10.0
R50: library part CMP-0017028-3, "RES, 4.87 k, 1%, 0.25 W, AEC-Q200 Grade 0, 1206", Manufacturer=Vishay-Dale, Power_W=250mW, Supplier Part Number 1=541-4.87KFCT-ND, TempCo="100 ppm/C", Tolerance_%=1%, Value2=0.25W, Value_Code=4k87, ValueDisplayed=4.87k
T1: library part CMP-0084101-1, "Transformer, 2500 uH, TH", Manufacturer="Wurth Elektronik", ValueDisplayed=2.5mH
TP1 TP2 TP3 TP4 TP5 TP7 TP8 TP9 TP10 TP11 TP12 TP13 TP14 TP15: library part CMP-0055162-1, "Test Point, Miniature, SMT", Manufacturer=Keystone, Supplier Part Number 1=36-5019TR-ND
U1: library part CMP-0066030-1, "Single-Output LDO, 800mA, Fixed (3.3), Internal Current Limit, Thermal Overload Protection, DCY0004A (SOT-223-4)", Alternate Manufacturer="Texas Instruments"
U2: library part CMP-0067235-2, "Constant-Voltage, Constant-Current Flyback Controller Using Opto-Coupler Feedback, D0007A (SOIC-7)", Alternate Manufacturer="Texas Instruments", Alternate PartNumber=UCC28740D
U3: library part CMP-0006158-3, "Optocoupler, 5 kV, 50-600% CTR, SMT", Manufacturer=Lite-On, Supplier Part Number 1=160-1367-5-ND, Voltage_Isolation_Vrms=5kV
U4: library part CMP-0033147-1, "Adjustable Precision Shunt Regulator, 34 ppm / degC, 100 mA, -40 to 85 degC, 3-pin SOT-23 (DBZ), Green (RoHS & no Sb/Br)", Manufacturer="Texas Instruments", Rating=Catalog, Temp Coeff(Max)(ppm/ degree C)=92, Temp Coeff(Typ)(ppm/ degree C)=34
ZZ1: library part CMP-0003616-3
ZZ2: library part CMP-0077236-1
ZZ3: library part CMP-0077237-1
ZZ4: library part CMP-0077238-1

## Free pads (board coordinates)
  oval 40x393.7 hole 40 slot 393.7 at 90 deg unplated mask+5: 1(777.37,2117)
  oval 40x236.22 hole 40 slot 236.22 at 90 deg unplated mask+5: 1(1171.22,2353)
  oval 295.28x40 hole 40 slot 295.28 at 135 deg unplated rot 135 mask+5: 1(1263.22,2163)
  oval 40x196.85 hole 40 slot 196.85 at 90 deg unplated mask+5: 1(2026.69,1282.5) 1(2389.69,1284.5)
  oval 157.48x40 hole 40 slot 157.48 at 135 deg unplated rot 135 mask+5: 1(2067.69,1161.5)
  oval 40x157.46 hole 40 slot 157.46 at 90 deg unplated mask+5: 1(2109.37,1060.19) 1(2306,1061.5)
  oval 236.22x40 hole 40 slot 236.22 at 0 deg unplated mask+5: 1(2207.69,991.63)
  oval 520x40 hole 40 slot 520 at 0 deg unplated mask+5: 1(2299.37,1707)
  oval 157.48x40 hole 40 slot 157.48 at 45 deg unplated rot 45 mask+5: 1(2348.69,1163.5)
  oval 40x472.44 hole 40 slot 472.44 at 90 deg unplated mask+5: 1(3748.22,211.5)

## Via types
v1: diameter 34, hole 16, Top Layer to Bottom Layer, tented both sides, 56 vias
v2: diameter 100, hole 60, Top Layer to Bottom Layer, tented both sides, 1 vias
